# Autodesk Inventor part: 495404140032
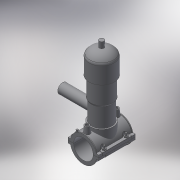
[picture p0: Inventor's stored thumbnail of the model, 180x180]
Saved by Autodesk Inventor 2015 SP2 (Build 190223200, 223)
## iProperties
Created: 2017-07
Part Number: 495404140032
Material: Generic
Description: PLASSON TAPPING VALVE 140-32
Document SubType Name: Modeling
Designer: KIM
Density: 1 g/cm^3
Appearance: Default
Author: KIM
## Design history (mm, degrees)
derived "495404-4954S4.ipt"
feature "Solid1::495404-4954S4.ipt"
feature "Solid2::495404-4954S4.ipt"
tag "TaggingFeature1"
body "Solid1"
body "Solid2"
other parameters: "d3" = 35, "d4" = 118, "d5" = 0, "d6" = 0.1, "d8" = 0, "d19" = 6, "d20" = 6, "d21" = 70.8, "d23" = 0, "d24" = 35.4, "d26" = 0, "d27" = 3, "d28" = 3, "d29" = 3, "d30" = 46.66667, "d31" = 6, "d32" = 0, "d33" = 0, "d34" = 0.6, "d40" = 87.36, "d70" = 15, "d72" = 0, "d73" = 6, "d75" = 5, "d76" = 0, "d77" = 7, "d79" = 15, "d80" = 47.2, "d82" = 5 deg, "d84" = 4, "d85" = 14, "d86" = 0, "d87" = 3, "d88" = 0, "d89" = 1, "d90" = 1, "d91" = 94.4, "d92" = 0, "d93" = 0.5, "d94" = 73.68421, "d96" = 173.04, "d97" = 2.36, "d98" = 0, "d120" = 140 deg, "d121" = 24.228, "d122" = 20 deg, "d123" = 336, "d124" = 100.8, "d126" = 0, "d143" = 144.2, "d145" = 21.53846, "d149" = 2.1, "d150" = 23.69231, "d153" = 118, "d154" = 0, "d156" = 84, "d157" = 160 deg, "d159" = 5.6, "d161" = 2.1, "d162" = 70.8, "d163" = 0, "d167" = 14, "d168" = 81.95122, "d170" = 3, "d172" = 0, "d173" = 1, "d176" = 20 deg, "d177" = 9.8, "d178" = 28, "d180" = 0, "d183" = 11.2, "d184" = 7.84, "d185" = 38.35, "d186" = 38.35, "d187" = 84, "d188" = 8.4, "d189" = 9.8, "d190" = 0, "d191" = 126, "d193" = 6.8, "d194" = 2.95, "d195" = 90 deg, "d197" = 0, "d199" = 0, "d205" = 14.64, "d206" = 81.33333, "d207" = 244, "d208" = 224.48, "d209" = 207.4, "d210" = 200.08, "d211" = 146.4, "d212" = 85.4, "d213" = 65.88, "d214" = 73.2, "d216" = 19.52, "d217" = 70.76, "d218" = 80.52, "d222" = 0, "d223" = 168, "d224" = 126, "d225" = 46, "d226" = 32, "d229" = 126, "d230" = 0, "H_" = 126, "L_" = 118, "d_t" = 6, "d_1" = 32, "H_1" = 46, "H_2" = 244, "d148" = 2.1, "d160" = 2.1, "d169" = 3, "d192" = 6.8, "d228" = 25.6
